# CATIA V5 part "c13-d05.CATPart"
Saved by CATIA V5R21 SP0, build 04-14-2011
Part number: Part1
Bounding box of the stored display mesh (mm): x -62.5 to 62.5, y -75 to 75, z 0 to 20
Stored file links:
  D:\CATIA V5R21 E-RESOURCES\CATIA-V5R21\catia-v5r21-Prts\c13_catia_v5r21_prt\c13_catia_v5r21_figr_13-22\c13-d05.CATPart
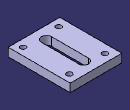
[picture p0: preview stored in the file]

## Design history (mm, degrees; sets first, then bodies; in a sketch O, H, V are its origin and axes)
Body1 (main body)
  Sketch1 on xy-plane, origin (0, 0, 0), H (1, 0, 0), V (0, 1, 0)
    line L1 (62.5, 75) -> (62.5, -75)
    line L2 (62.5, -75) -> (-62.5, -75)
    line L3 (-62.5, -75) -> (-62.5, 75)
    line L4 (-62.5, 75) -> (62.5, 75)
    length L1 = 150
    length L2 = 125
    vertical: L1 V, L3 V
    horizontal: L2 H, L4 H
    equidistance: L1 L3 O, L2 L4 O
  Pad1: profile Sketch1, direction (0, 0, 1), length 20
  Sketch2 on face of Pad1, origin (0, 0, 20), H (1, 0, 0), V (0, 1, 0)
    construction line L1 (0, 45) -> (0, -45)
    point P1 (0, 45)
    line L2 (12, 45) -> (12, -45)
    line L3 (-12, -45) -> (-12, 45)
    arc A1 centre (0, -45) radius 12 from (12, -45) to (-12, -45) cw
    arc A2 centre (0, 45) radius 12 from (-12, 45) to (12, 45) cw
    length L1 = 90
    radius A2 = 12
    coincidence: P1 V
    vertical: L1 V
    tangency: A1 L2, A2 L2, A1 L3, A2 L3
    parallelism: L1 L2
    midpoint: O L1
  Pocket1: profile Sketch2, direction (0, 0, -1), through (limit type 3)
  Sketch3 on face of Pad1, origin (38.7626, -18.4621, 20), H (1, 0, 0), V (0, 1, 0)
    point P1 (5.7374, -38.5379)
    reference projected line E1 (-101.2626, -56.5379) -> (23.7374, -56.5379) from edge [face of Pad1 | face of Pad1]
    reference projected line E2 (23.7374, -56.5379) -> (23.7374, 93.4621) from edge [face of Pad1 | face of Pad1]
    distance P1 E1 = 18
    distance P1 E2 = 18
  Hole1: placed by Sketch3, at (44.5, -57, 20) direction (0, 0, -1), diameter 13, through (limit type 3)
  RectPattern1: of Hole1, direction 1 instances 2, spacing 86, along edge [face of Pad1 | face of Pad1] reversed, direction 2 instances 2, spacing 112, along edge [face of Pad1 | face of Pad1]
